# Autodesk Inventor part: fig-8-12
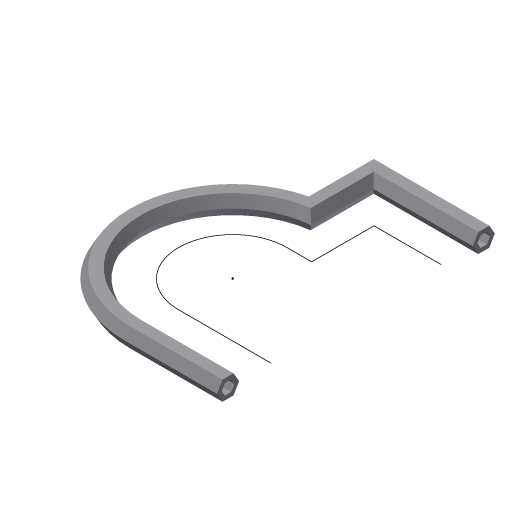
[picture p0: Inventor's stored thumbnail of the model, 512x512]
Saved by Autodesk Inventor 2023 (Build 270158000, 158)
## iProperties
Created: 2004-05
Part Number: fig-8-12
Document SubType Name: Modeling
Designer: CADCIM Technologies
Manufacturer: Standard
Standards Organization: Custom
Density: 1 g/cm^3
Material: Generic
Appearance: Default
Author: CADCIM Technologies
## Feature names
1. Sweep5
## Parameters: d4 = 0, d5 = 0
